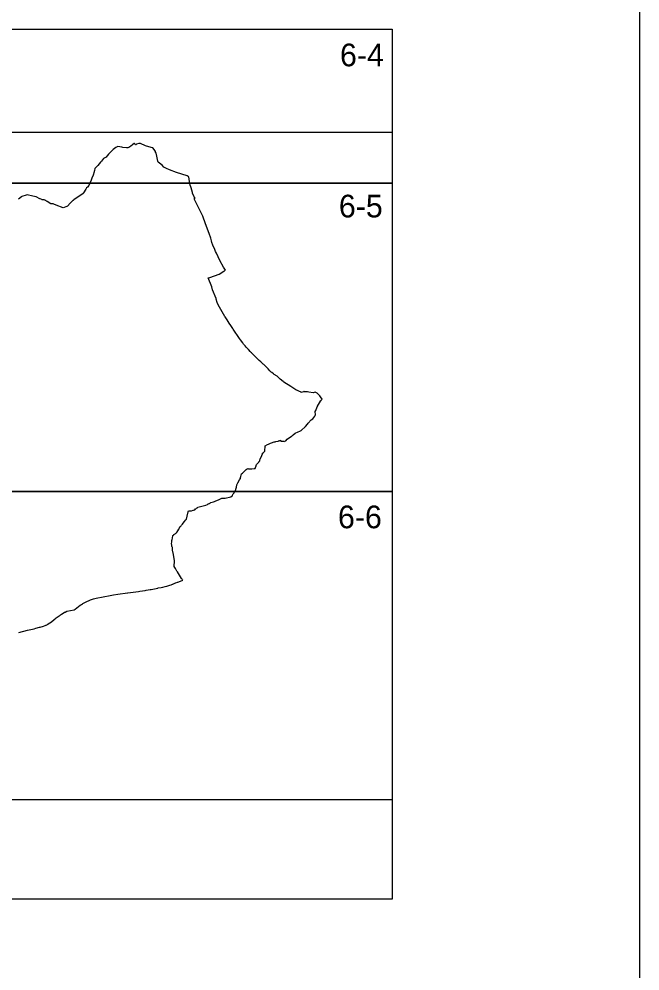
# Model space of a CAD drawing. Extents: x -447352 to -425530, y -1135906 to -1121091.
# Drawn here: x -441930 to -441678.4, y -1122276.2 to -1121890.1 of the extents above; entities that cross this region are included whole.
import ezdxf

# ---------------------------------------------------------------- set-up
doc = ezdxf.new("R2010")
doc.units = 0
for name, color, linetype in [('Vrstva 1', 7, 'Continuous'), ('Vrstva 10', 7, 'Continuous'), ('Vrstva 4', 7, 'Continuous')]:
    doc.layers.add(name, color=color, linetype=linetype)

msp = doc.modelspace()

# ---------------------------------------------------------------- linework, layer by layer
at = {"layer": 'Vrstva 1'}
msp.add_lwpolyline([(-443163.41, -1121535.97), (-443163.41, -1122585.97), (-441678.41, -1122585.97), (-441678.41, -1121535.97)], close=True, dxfattribs=at)
msp.add_lwpolyline([(-441930.12, -1122138.88), (-441926.58, -1122138.01), (-441923.81, -1122137.34), (-441923.14, -1122137.13), (-441921.65, -1122136.77), (-441921.44, -1122136.71), (-441920.01, -1122136.32), (-441919.41, -1122136.06), (-441919.19, -1122135.96), (-441919.03, -1122135.9), (-441918.21, -1122135.45), (-441918.15, -1122135.41), (-441916.84, -1122134.63), (-441915.69, -1122133.58), (-441915.04, -1122133.08), (-441914.91, -1122132.97), (-441914.89, -1122132.96), (-441914.73, -1122132.83), (-441914.58, -1122132.73), (-441913.78, -1122132.17), (-441913.72, -1122132.13), (-441913.65, -1122132.08), (-441913.14, -1122131.73), (-441912.77, -1122131.47), (-441912.11, -1122131.01), (-441911.52, -1122130.6), (-441911.36, -1122130.63), (-441911.35, -1122130.63), (-441911.33, -1122130.61), (-441910.6, -1122130.22), (-441907.64, -1122129.64), (-441907.22, -1122129.49), (-441905.19, -1122127.86), (-441904.72, -1122127.52), (-441904.69, -1122127.5), (-441904.33, -1122127.24), (-441904.15, -1122127.12), (-441902.76, -1122126.42), (-441901.35, -1122125.78), (-441901.05, -1122125.63), (-441899.79, -1122125.17), (-441898.79, -1122124.92), (-441893.08, -1122123.86), (-441891.66, -1122123.6), (-441889.95, -1122123.35), (-441886.08, -1122122.78), (-441885.84, -1122122.75), (-441881.54, -1122122.23), (-441881.01, -1122122.17), (-441878.86, -1122121.81), (-441878.54, -1122121.76), (-441876.88, -1122121.49), (-441876.48, -1122121.42), (-441875.07, -1122121.13), (-441873.78, -1122120.86), (-441873.57, -1122120.82), (-441872.4, -1122120.59), (-441871.73, -1122120.46), (-441871.71, -1122120.46), (-441870.8, -1122120.25), (-441870.73, -1122120.23), (-441870.08, -1122120.07), (-441869.73, -1122119.96), (-441868.84, -1122119.67), (-441868.4, -1122119.52), (-441867.75, -1122119.28), (-441867.63, -1122119.24), (-441866.54, -1122118.75), (-441866.54, -1122118.75), (-441866.42, -1122118.71), (-441865.77, -1122118.48), (-441865.68, -1122118.45), (-441865.25, -1122118.29), (-441863.59, -1122117.71), (-441863.61, -1122117.66), (-441863.72, -1122117.49), (-441863.88, -1122117.26), (-441864.1, -1122116.94), (-441865.8, -1122114.3), (-441866.01, -1122113.95), (-441866.18, -1122113.68), (-441866.62, -1122112.97), (-441867.15, -1122112.12), (-441866.99, -1122109.76), (-441866.98, -1122109.67), (-441867.37, -1122107.37), (-441867.37, -1122107.35), (-441867.38, -1122107.33), (-441867.38, -1122107.33), (-441867.38, -1122107.3), (-441867.79, -1122105.47), (-441867.8, -1122105.28), (-441867.86, -1122104.48), (-441867.96, -1122104.2), (-441867.97, -1122104.18), (-441868.08, -1122103.96), (-441868.12, -1122103.88), (-441868.13, -1122103.5), (-441868.16, -1122102.8), (-441868.11, -1122102.31), (-441868.11, -1122102.29), (-441868.02, -1122101.43), (-441868, -1122101.32), (-441867.71, -1122099.68), (-441867.63, -1122099.6), (-441867.33, -1122099.26), (-441867.27, -1122099.19), (-441867.01, -1122099.07), (-441866.95, -1122099.01), (-441866.69, -1122098.81), (-441866.46, -1122098.63), (-441866.25, -1122098.47), (-441866.19, -1122098.43), (-441866.11, -1122098.3), (-441866.03, -1122098.18), (-441865.92, -1122098.01), (-441865.7, -1122097.68), (-441865.28, -1122097.03), (-441865.15, -1122096.78), (-441865.14, -1122096.77), (-441865, -1122096.48), (-441864.95, -1122096.39), (-441864.77, -1122096.06), (-441864.63, -1122095.91), (-441864.33, -1122095.6), (-441864.16, -1122095.42), (-441863.88, -1122095.07), (-441863.75, -1122094.9), (-441863.06, -1122094.05), (-441862.4, -1122093.24), (-441862.11, -1122092.88), (-441861.87, -1122091.71), (-441861.81, -1122091.48), (-441861.74, -1122091.2), (-441861.42, -1122089.89), (-441861.34, -1122089.61), (-441861.34, -1122089.58), (-441861.32, -1122089.53), (-441861.16, -1122089.52), (-441861.14, -1122089.52), (-441860.9, -1122089.52), (-441860.21, -1122089.5), (-441860.2, -1122089.5), (-441860.17, -1122089.5), (-441859.49, -1122089.32), (-441859.29, -1122089.26), (-441858.87, -1122089.15), (-441858.85, -1122089.14), (-441858.79, -1122089.08), (-441858.49, -1122088.8), (-441858.37, -1122088.72), (-441858.03, -1122088.46), (-441857.61, -1122088.14), (-441857.54, -1122088.12), (-441856.98, -1122087.96), (-441854.28, -1122087.2), (-441853.69, -1122086.93), (-441853.36, -1122086.77), (-441853.31, -1122086.75), (-441853.21, -1122086.7), (-441852.85, -1122086.52), (-441852.8, -1122086.5), (-441852.77, -1122086.48), (-441852.76, -1122086.48), (-441852.73, -1122086.46), (-441852.42, -1122086.31), (-441852.36, -1122086.27), (-441852.25, -1122086.22), (-441851.17, -1122085.89), (-441850.74, -1122085.71), (-441850.22, -1122085.49), (-441849.21, -1122085.08), (-441847.79, -1122084.45), (-441847.65, -1122084.44), (-441846.52, -1122084.39), (-441844.12, -1122083.83), (-441843.59, -1122083.43), (-441843.52, -1122083.31), (-441843.43, -1122083.13), (-441843.17, -1122082.62), (-441842.82, -1122082.19), (-441842.8, -1122082.16), (-441842.59, -1122081.87), (-441842.48, -1122081.71), (-441842.47, -1122081.7), (-441841.93, -1122079.92), (-441841.92, -1122079.89), (-441841.72, -1122078.94), (-441841.46, -1122078.48), (-441841.27, -1122078.15), (-441840.72, -1122077.03), (-441840.34, -1122076.52), (-441840.31, -1122076.39), (-441840.24, -1122076.09), (-441840.21, -1122075.95), (-441840.15, -1122075.7), (-441840.13, -1122075.6), (-441839.81, -1122074.59), (-441839.8, -1122074.58), (-441839.51, -1122074.3), (-441838.85, -1122073.67), (-441838.8, -1122073.62), (-441838.33, -1122073.14), (-441838.07, -1122072.88), (-441837.97, -1122072.77), (-441837.6, -1122072.45), (-441837.56, -1122072.45), (-441837.55, -1122072.45), (-441837.14, -1122072.44), (-441836.97, -1122072.45), (-441836.34, -1122072.47), (-441835.63, -1122072.47), (-441834.66, -1122072.38), (-441834.63, -1122072.38), (-441834.38, -1122072.35), (-441834.16, -1122071.99), (-441834.11, -1122071.86), (-441834.09, -1122071.81), (-441834.07, -1122071.75), (-441833.71, -1122070.73), (-441833.57, -1122070.56), (-441833.47, -1122070.45), (-441833.43, -1122070.41), (-441833.37, -1122070.33), (-441833.25, -1122070.2), (-441832.98, -1122069.88), (-441832.89, -1122069.78), (-441832.79, -1122069.66), (-441832.45, -1122069.27), (-441832.38, -1122068.88), (-441832.32, -1122068.57), (-441832.25, -1122068.44), (-441831.7, -1122067.52), (-441831.59, -1122067.13), (-441831.4, -1122066.43), (-441831.28, -1122066.14), (-441830.99, -1122065.87), (-441830.44, -1122065.36), (-441830.37, -1122065.3), (-441830.27, -1122063.19), (-441829.25, -1122062.7), (-441828.85, -1122062.49), (-441828.6, -1122062.36), (-441828.31, -1122062.2), (-441828.09, -1122062.12), (-441827.75, -1122061.99), (-441827.7, -1122061.98), (-441826.61, -1122061.57), (-441826.6, -1122061.57), (-441826.11, -1122061.51), (-441826.03, -1122061.49), (-441825, -1122061.23), (-441824.85, -1122061.19), (-441824.76, -1122061.16), (-441824.59, -1122061.11), (-441824.06, -1122060.94), (-441824.06, -1122060.94), (-441824.05, -1122060.95), (-441824.05, -1122060.95), (-441824.02, -1122061.01), (-441823.89, -1122061.23), (-441823.01, -1122061.33), (-441822.81, -1122061.35), (-441822.45, -1122061.39), (-441822.36, -1122061.35), (-441821.93, -1122061.17), (-441821.28, -1122060.46), (-441819.64, -1122059.3), (-441819.55, -1122059.23), (-441819.38, -1122059.12), (-441818.87, -1122058.7), (-441818.12, -1122058.1), (-441816.85, -1122057.53), (-441816.23, -1122057.26), (-441815.69, -1122057.02), (-441815.63, -1122056.99), (-441813.98, -1122055.32), (-441813.14, -1122054.43), (-441812.78, -1122054.05), (-441811.59, -1122052.69), (-441810.99, -1122052.23), (-441810.94, -1122052.19), (-441810.1, -1122051.18), (-441809.9, -1122050.61), (-441809.99, -1122049.28), (-441809.77, -1122048.79), (-441809.13, -1122047.34), (-441807.67, -1122044.86), (-441807.64, -1122044.81), (-441807.64, -1122044.81), (-441807.62, -1122044.78), (-441807.59, -1122044.74), (-441807.44, -1122044.55), (-441807.18, -1122044.21), (-441807.44, -1122043.91), (-441807.58, -1122043.69), (-441808.05, -1122042.95), (-441808.25, -1122042.76), (-441808.4, -1122042.6), (-441808.59, -1122042.4), (-441809.17, -1122041.83), (-441810.02, -1122041.36), (-441810.47, -1122041.54), (-441810.8, -1122041.66), (-441812.55, -1122041.39), (-441813.16, -1122041.3), (-441813.3, -1122041.29), (-441813.89, -1122041.27), (-441814.27, -1122041.22), (-441814.43, -1122041.19), (-441814.47, -1122041.19), (-441814.5, -1122041.18), (-441814.5, -1122041.18), (-441814.53, -1122041.19), (-441814.63, -1122041.22), (-441814.76, -1122041.25), (-441815.66, -1122041.49), (-441815.73, -1122041.46), (-441817.8, -1122040.42), (-441819.82, -1122039.14), (-441822.73, -1122037.32), (-441822.89, -1122037.18), (-441822.93, -1122037.15), (-441823.02, -1122037.07), (-441824.16, -1122036.14), (-441825.31, -1122035.09), (-441825.42, -1122034.99), (-441826.63, -1122034.23), (-441826.91, -1122034), (-441827.54, -1122033.5), (-441827.85, -1122033.26), (-441828.35, -1122032.73), (-441829.07, -1122031.97), (-441829.22, -1122031.81), (-441829.68, -1122031.32), (-441830.65, -1122030.29), (-441830.85, -1122030.18), (-441830.85, -1122030.18), (-441831.03, -1122030.09), (-441831.23, -1122029.99), (-441832.06, -1122029.16), (-441832.69, -1122028.53), (-441833.87, -1122027.36), (-441834.8, -1122026.42), (-441834.96, -1122026.27), (-441835.4, -1122025.82), (-441835.64, -1122025.58), (-441835.73, -1122025.49), (-441835.77, -1122025.45), (-441836.29, -1122024.93), (-441836.93, -1122024.28), (-441837.01, -1122024.2), (-441837.03, -1122024.18), (-441837.18, -1122024.03), (-441838.01, -1122023.19), (-441838.39, -1122022.69), (-441838.67, -1122022.32), (-441838.99, -1122021.89), (-441839.35, -1122021.41), (-441840.3, -1122020.15), (-441840.67, -1122019.61), (-441843.21, -1122015.87), (-441843.38, -1122015.61), (-441844.15, -1122014.42), (-441844.82, -1122013.41), (-441845.66, -1122012.08), (-441846.46, -1122010.81), (-441846.54, -1122010.68), (-441847.63, -1122008.83), (-441849.31, -1122005.98), (-441849.31, -1122005.97), (-441849.31, -1122005.97), (-441849.32, -1122005.97), (-441849.65, -1122004.99), (-441850.1, -1122003.69), (-441850.16, -1122003.49), (-441851.54, -1121999.98), (-441851.83, -1121998.73), (-441853.31, -1121995.05), (-441852.68, -1121994.85), (-441848.96, -1121993.61), (-441846.99, -1121992.39), (-441846.81, -1121992.28), (-441846.75, -1121992.24), (-441846.55, -1121992.12), (-441846.28, -1121991.95), (-441847.2, -1121990.76), (-441848.61, -1121987.98), (-441849.36, -1121986.51), (-441849.89, -1121985.35), (-441849.91, -1121985.31), (-441849.97, -1121985.18), (-441849.98, -1121985.15), (-441850, -1121985.12), (-441850.04, -1121985.03), (-441850.37, -1121984.3), (-441850.69, -1121983.51), (-441851.4, -1121981.74), (-441851.81, -1121980.7), (-441851.96, -1121980.07), (-441852.22, -1121978.94), (-441852.96, -1121977.05), (-441853.16, -1121976.45), (-441854.1, -1121973.82), (-441854.37, -1121973.1), (-441855.56, -1121970.01), (-441855.63, -1121969.83), (-441855.66, -1121969.75), (-441859.01, -1121962.94), (-441858.7, -1121962.8), (-441858.68, -1121962.79), (-441858.78, -1121962.62), (-441858.86, -1121962.52), (-441859.03, -1121962.29), (-441859.09, -1121962.21), (-441859.7, -1121960.73), (-441859.75, -1121960.44), (-441859.85, -1121959.98), (-441859.86, -1121959.92), (-441860.37, -1121958.08), (-441860.67, -1121957.45), (-441860.68, -1121957.37), (-441860.72, -1121957.01), (-441860.86, -1121955.92), (-441861.14, -1121954.08), (-441861.2, -1121954.06), (-441861.5, -1121953.96), (-441861.88, -1121953.7), (-441861.89, -1121953.7), (-441866.19, -1121952.29), (-441868.98, -1121951.31), (-441870.29, -1121950.69), (-441871.26, -1121950.13), (-441871.98, -1121949.35), (-441873.66, -1121948.08), (-441873.72, -1121947.78), (-441874.3, -1121945.08), (-441874.45, -1121944.54), (-441874.63, -1121944.03), (-441874.68, -1121943.87), (-441874.93, -1121943.35), (-441875.18, -1121943.04), (-441875.76, -1121942.35), (-441876.51, -1121942.14), (-441878.69, -1121941.48), (-441880.78, -1121940.52), (-441881.4, -1121940.52), (-441882.35, -1121940.89), (-441882.48, -1121940.98), (-441882.55, -1121941.03), (-441882.69, -1121941.13), (-441882.73, -1121941.16), (-441882.75, -1121941.14), (-441882.96, -1121940.89), (-441883.21, -1121940.61), (-441883.29, -1121940.51), (-441883.38, -1121940.55), (-441883.89, -1121940.94), (-441884.08, -1121941.09), (-441884.75, -1121941.61), (-441885.5, -1121942.17), (-441885.84, -1121942.39), (-441886.43, -1121942.35), (-441887.91, -1121942.2), (-441888.37, -1121942.11), (-441889.96, -1121941.79), (-441890.26, -1121941.9), (-441890.82, -1121942.25), (-441891.37, -1121942.57), (-441891.86, -1121943.03), (-441892.39, -1121943.52), (-441892.79, -1121943.91), (-441892.8, -1121943.92), (-441893.13, -1121944.26), (-441893.26, -1121944.4), (-441893.77, -1121944.95), (-441894.22, -1121945.5), (-441894.38, -1121945.69), (-441894.74, -1121946.12), (-441895.48, -1121946.45), (-441895.5, -1121946.45), (-441895.7, -1121946.7), (-441896.56, -1121947.72), (-441896.94, -1121948.17), (-441898.07, -1121949.53), (-441898.08, -1121949.54), (-441899.32, -1121950.71), (-441899.44, -1121951.55), (-441899.49, -1121951.92), (-441899.53, -1121952.02), (-441900.01, -1121953.37), (-441900.45, -1121954.61), (-441900.48, -1121954.69), (-441900.78, -1121955.38), (-441901.71, -1121957.56), (-441901.73, -1121957.57), (-441902.3, -1121958.25), (-441902.6, -1121958.6), (-441902.6, -1121958.61), (-441902.94, -1121959.15), (-441903.81, -1121960.54), (-441903.9, -1121960.68), (-441904.07, -1121960.81), (-441904.6, -1121961.2), (-441905.21, -1121961.65), (-441905.21, -1121961.65), (-441906.18, -1121962.28), (-441906.31, -1121962.37), (-441906.49, -1121962.49), (-441907.79, -1121963.35), (-441907.8, -1121963.36), (-441908.06, -1121963.62), (-441908.18, -1121963.74), (-441908.4, -1121963.97), (-441908.68, -1121964.25), (-441909.25, -1121964.82), (-441910.41, -1121965.98), (-441910.61, -1121966.06), (-441912.11, -1121966.63), (-441914.92, -1121965.51), (-441914.92, -1121965.52), (-441914.93, -1121965.54), (-441915.84, -1121965.16), (-441916.15, -1121965.03), (-441916.17, -1121965.03), (-441916.56, -1121965.03), (-441917.04, -1121965.03), (-441918.6, -1121964.04), (-441918.86, -1121963.91), (-441919.15, -1121963.75), (-441919.21, -1121963.72), (-441919.25, -1121963.7), (-441919.79, -1121963.47), (-441919.84, -1121963.47), (-441919.85, -1121963.47), (-441920, -1121963.46), (-441920.12, -1121963.45), (-441920.43, -1121963.43), (-441920.45, -1121963.43), (-441920.45, -1121963.43), (-441920.56, -1121963.39), (-441920.8, -1121963.29), (-441921.4, -1121963.04), (-441921.56, -1121962.97), (-441923.08, -1121962.24), (-441923.7, -1121962.06), (-441924.37, -1121961.86), (-441926.69, -1121961.43), (-441926.7, -1121961.43), (-441927.1, -1121961.54), (-441928.84, -1121962.12), (-441928.97, -1121962.23), (-441930.18, -1121963.19)], dxfattribs=at)
at = {"layer": 'Vrstva 10'}
msp.add_lwpolyline([(-441778.82, -1121936.02), (-441778.82, -1122247), (-442111.69, -1122247), (-442111.69, -1122081.7), (-442091.32, -1122081.7), (-442091.32, -1121956.7), (-442091.32, -1121936.02), (-441778.82, -1121936.02)], dxfattribs=at)
at = {"layer": 'Vrstva 4'}
msp.add_line((-442091.32, -1121894.2), (-441778.82, -1121894.2), dxfattribs=at)
msp.add_lwpolyline([(-441778.82, -1121894.2), (-441778.82, -1121956.7), (-441935.07, -1121956.7), (-441935.07, -1121894.2)], dxfattribs=at)
for points in [[(-441778.82, -1121956.7), (-441778.82, -1122081.7), (-441935.07, -1122081.7), (-441935.07, -1121956.7)], [(-441778.82, -1122081.7), (-441778.82, -1122206.7), (-441935.07, -1122206.7), (-441935.07, -1122081.7)]]:
    msp.add_lwpolyline(points, close=True, dxfattribs=at)

# ---------------------------------------------------------------- texts
at = {"layer": 'Vrstva 1'}
for s, p in [('6-4', (-441799.95, -1121909.25)), ('6-5', (-441800.4, -1121970.54)), ('6-6', (-441800.77, -1122096.61))]:
    msp.add_text(s, height=9.2, dxfattribs=at).set_placement(p)

doc.saveas('drawing.dxf')
